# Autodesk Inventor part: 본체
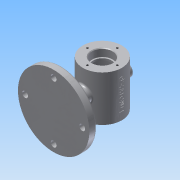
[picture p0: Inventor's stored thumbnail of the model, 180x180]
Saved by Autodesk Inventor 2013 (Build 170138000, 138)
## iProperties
Created: 2018-12
Part Number: 본체
Material: 알루미늄 6061
Document SubType Name: Modeling
Designer: Administrator
Density: 2.71 g/cm^3
Mass: 687.623 g
Surface Area: 555.481 cm^2
Volume: 253.735 cm^3
Author: Administrator
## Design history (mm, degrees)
sketch "스케치1"
  geometry: C1 r 30 at (0, 0); 1 further point
  constraints: 1 centre point, 1 coincident
  dimensions: "d0" = 30 radius of C1
extrude "돌출1" new body sketch "스케치1" distance "d1" = 35; taper "d2" = 0 deg
sketch "스케치2"
  geometry: C1 r 16 at (0, 0); 1 further point
  constraints: 1 centre point, 1 coincident
  dimensions: "d3" = 16 radius of C1
extrude "돌출2" cut sketch "스케치2" distance "d4" = 12; taper "d5" = 0 deg
sketch "스케치3"
  geometry: C1 r 14 at (0, 0); 1 further point
  constraints: 1 centre point, 1 coincident
  dimensions: "d6" = 14 radius of C1
extrude "돌출3" cut sketch "스케치3" distance "d7" = 3; taper "d8" = 0 deg
sketch "스케치4"
  geometry: C1 r 25 at (0, 0); 1 further point
  constraints: 1 centre point, 1 coincident
  dimensions: "d9" = 25 radius of C1
extrude "돌출4" cut sketch "스케치4" distance "d10" = 20; taper "d11" = 0 deg
sketch "스케치5"
  geometry: C1 r 16 at (0, 0) reference; 2 further points
  constraints: 1 vertical alignment
  dimensions: "d12" = 23 distance of point (0, 23) point (0, 0)
hole "구멍1" sketch "스케치5" at (0, 23) diameter "d13" = 3.242; stored, may be unused: countersink angle "d17" = 90 deg, drill point angle "d19" = 118 deg; dims "d14" = 8, "d15" = 4, "d16" = 2, "d18" = 10
node "작업 평면1"
sketch "스케치6"
  geometry: C1 r 55 at (0, 0); 1 further point
  constraints: 1 centre point, 1 coincident
  dimensions: "d24" = 55 radius of C1
extrude "돌출5" join sketch "스케치6" distance "d25" = 11; taper "d26" = 0 deg
sketch "스케치7"
  geometry: C1 r 12 at (0, 0); 1 further point
  constraints: 1 centre point, 1 coincident
  dimensions: "d28" = 12 radius of C1
extrude "돌출6" join sketch "스케치7" stored distance "d29" = 11; taper "d30" = 0 deg
sketch "스케치8"
  geometry: C1 r 55 at (0, 0) reference; 2 further points
  constraints: 1 vertical alignment
  dimensions: "d53" = 44 distance of point (0, 44) point (0, 0)
extrude "돌출7" join sketch "스케치8" distance "d31" = 15; taper "d32" = -75 deg
node "작업 평면2"
sketch "스케치9"
  geometry: C1 r 10 at (0, 0); 1 further point
  constraints: 1 centre point, 1 coincident
  dimensions: "d34" = 10 radius of C1
extrude "돌출8" join sketch "스케치9" stored distance "d35" = 15; taper "d36" = 0 deg
hole "구멍2" diameter "d39" = 10; stored, may be unused: countersink angle "d43" = 90 deg, drill point angle "d45" = 118 deg; dims "d37" = 10, "d38" = 10, "d40" = 8, "d41" = 4, "d42" = 2, "d44" = 10
node "작업 평면4"
sketch "스케치11"
  geometry: L1 (30, 35)-(-30, 35) reference; L2 (30, -35)-(30, 35) reference; 2 further points
  constraints: 1 other
  dimensions: "d48" = 35 distance from line of point (0, 0) L1; "d49" = 30 distance from line of point (0, 0) L2
feature "엠보싱1" sketch "스케치11" dims "d50" = 0.5, "d51" = 0
sketch "스케치15"
  geometry: C1 r 4.5 at (0, 44); 1 further point
  constraints: 1 centre point, 1 vertical alignment
  dimensions: "d68" = 9 diameter of C1; "d69" = 44 distance of C1.centre point (0, 0)
extrude "돌출9" cut sketch "스케치15" distance "d70" = 20; taper "d71" = 0 deg
node "작업 평면6"
sketch "스케치16"
  geometry: C1 r 4.5 at (0, 44) reference; C2 r 7 at (0, 44); 1 further point
  constraints: 1 centre point, 1 coincident
  dimensions: "d73" = 14 diameter of C2
extrude "돌출10" cut sketch "스케치16" distance "d74" = 20; taper "d75" = 0 deg
fillet "모깎기1" dims "d79" = 3
fillet "모깎기2" dims "d80" = 3
fillet "모깎기3" dims "d81" = 3
chamfer "모따기1" distance "d82" = 1; stored, may be unused: second distance "d83" = 2, angle "d84" = 45 deg
fillet "모깎기4" dims "d85" = 3
fillet "모깎기5" dims "d86" = 0.3
chamfer "모따기2" distance "d87" = 1; stored, may be unused: second distance "d88" = 2, angle "d89" = 45 deg
node "솔리드1"
mirror "대칭1"
pattern_circular "원형 패턴1" dims angle "d21" = 360 deg
mirror "대칭2"
pattern_circular "원형 패턴2" dims angle "d77" = 360 deg
other parameters: "d23" = -75, "d33" = -112, "d47" = 47
